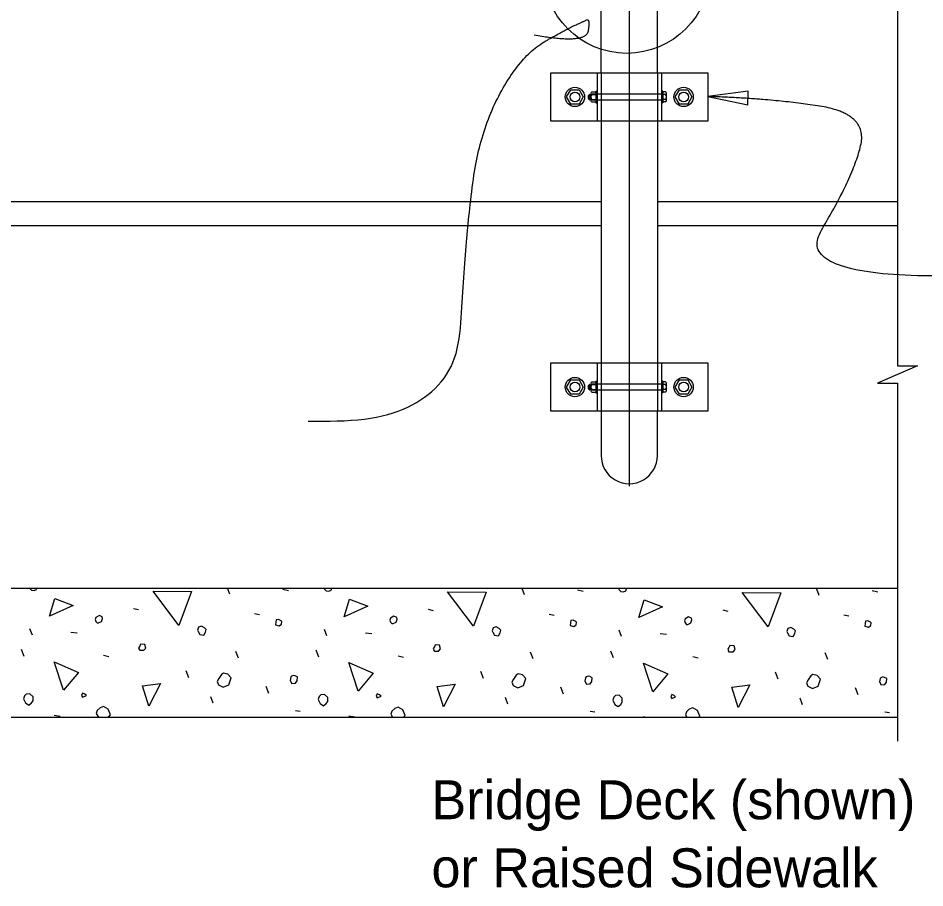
# Model space of a CAD drawing. Extents: x 0.5 to 39.7, y 0.9 to 25.6.
# Drawn here: x 19.046 to 23.735, y 12.586 to 17.084 of the extents above; entities that cross this region are included whole.
import ezdxf

# ---------------------------------------------------------------- set-up
doc = ezdxf.new("R2010")
doc.units = 0
for name, color, linetype in [('CL_Major', 7, 'Continuous'), ('Dimension', 7, 'Continuous'), ('Miscellaneous', 7, 'Continuous'), ('SteelMisc', 7, 'Continuous'), ('SteelMisc_h', 7, 'Continuous'), ('SupstrConc', 7, 'Continuous')]:
    doc.layers.add(name, color=color, linetype=linetype)

msp = doc.modelspace()

# ---------------------------------------------------------------- linework, layer by layer
at = {"layer": 'CL_Major'}
msp.add_line((22.2062, 25.5043), (22.2062, 14.6639), dxfattribs=at)
at = {"layer": 'Dimension'}
for points in [[(23.5932, 20.1983), (23.5932, 19.1806), (23.6966, 19.1806), (23.5932, 19.1356), (23.4899, 19.0906), (23.5932, 19.0906), (23.5932, 16.8862)], [(23.5932, 17.1362), (23.5932, 15.2854), (23.6966, 15.2854), (23.5932, 15.2404), (23.4899, 15.1954), (23.5932, 15.1954), (23.5932, 13.3448)]]:
    msp.add_lwpolyline(points, dxfattribs=at)
msp.add_lwpolyline([(22.6122, 16.6783), (22.819, 16.6352), (22.8216, 16.7057)], close=True, dxfattribs=at)
msp.add_circle((22.1934, 17.3332), 0.4318, dxfattribs=at)
for points in [[(20.5456, 14.9991), (21.3049, 14.9652), (21.3652, 16.0213), (21.4405, 16.5191), (21.6515, 16.8963), (21.8903, 17.0313), (21.9647, 17.0631), (22.0043, 17.0848), (21.982, 16.9466), (21.7151, 16.9952)], [(23.9932, 15.7529), (23.0399, 15.7236), (23.3618, 16.2556), (23.4433, 16.5898), (22.9335, 16.6682), (22.6122, 16.6783)]]:
    msp.add_open_spline(points, degree=2, dxfattribs=at)
at = {"layer": 'Miscellaneous'}
for p, q in [((21.9986, 16.6691), (21.9986, 16.6812)), ((22.0044, 16.6691), (22.0044, 16.6812)), ((21.9986, 15.1691), (21.9986, 15.1812)), ((22.0044, 15.1691), (22.0044, 15.1812)), ((20.141, 14.1043), (20.1292, 14.1361)), ((20.415, 14.1308), (20.4432, 14.1237)), ((21.6648, 14.1008), (21.6524, 14.1344)), ((21.9388, 14.1273), (21.9671, 14.1202)), ((23.1886, 14.0972), (23.1762, 14.1308)), ((23.4626, 14.1237), (23.4909, 14.1167)), ((19.6424, 14.0301), (19.669, 14.0247)), ((21.1663, 14.0265), (21.1928, 14.0212)), ((22.6901, 14.023), (22.7166, 14.0177)), ((20.2682, 14.0053), (20.2947, 14)), ((21.792, 14.0018), (21.8186, 13.9965)), ((23.3159, 13.9982), (23.3424, 13.9929)), ((19.1192, 13.8922), (19.1068, 13.9258)), ((19.3189, 13.9081), (19.3508, 13.9045)), ((20.643, 13.8886), (20.6306, 13.9222)), ((20.8428, 13.9045), (20.8746, 13.901)), ((22.1668, 13.8851), (22.1544, 13.9187)), ((22.3666, 13.901), (22.3984, 13.8975)), ((19.0768, 13.7826), (19.0626, 13.8179)), ((19.4869, 13.7896), (19.5152, 13.7826)), ((20.1851, 13.7737), (20.171, 13.8091)), ((20.6006, 13.779), (20.5864, 13.8144)), ((21.0107, 13.7861), (21.039, 13.779)), ((21.709, 13.7702), (21.6948, 13.8055)), ((22.1244, 13.7755), (22.1102, 13.8108)), ((23.2328, 13.7667), (23.2186, 13.802)), ((22.5345, 13.7826), (22.5628, 13.7755)), ((19.9288, 13.673), (19.9147, 13.7083)), ((21.4526, 13.6694), (21.4385, 13.7048)), ((22.9765, 13.6659), (22.9623, 13.7012)), ((20.3425, 13.5916), (20.3283, 13.627)), ((21.8663, 13.5881), (21.8522, 13.6235)), ((23.3901, 13.5846), (23.376, 13.6199)), ((20.0543, 13.5404), (20.042, 13.574)), ((21.5781, 13.5368), (21.5658, 13.5704)), ((23.102, 13.5333), (23.0896, 13.5669)), ((19.2323, 13.4785), (19.2624, 13.4732)), ((20.4804, 13.5033), (20.5051, 13.4997)), ((20.7561, 13.475), (20.7862, 13.4697)), ((22.0042, 13.4997), (22.0289, 13.4962)), ((22.28, 13.4714), (22.2912, 13.4695)), ((23.528, 13.4962), (23.5527, 13.4927))]:
    msp.add_line(p, q, dxfattribs=at)
for points in [[(19.105, 14.1361), (19.1156, 14.1255)], [(19.1156, 14.1255), (19.128, 14.1237), (19.1404, 14.129), (19.1428, 14.1361)], [(19.8776, 13.9434), (19.7432, 14.1202), (19.943, 14.1184), (19.8776, 13.9434)], [(20.63, 14.1361), (20.6289, 14.1326), (20.6395, 14.122)], [(20.6395, 14.122), (20.6518, 14.1202), (20.6642, 14.1255), (20.6677, 14.1361)], [(21.4014, 13.9399), (21.267, 14.1167), (21.4668, 14.1149), (21.4014, 13.9399)], [(22.155, 14.1361), (22.1527, 14.129), (22.1633, 14.1184)], [(22.1633, 14.1184), (22.1757, 14.1167), (22.188, 14.122), (22.1916, 14.1326), (22.1894, 14.1361)], [(19.2076, 13.9912), (19.2359, 14.0831), (19.3295, 14.046), (19.2076, 13.9912)], [(20.7314, 13.9876), (20.7597, 14.0796), (20.8534, 14.0424), (20.7314, 13.9876)], [(22.2552, 13.9841), (22.2835, 14.076), (22.3772, 14.0389), (22.2552, 13.9841)], [(22.9252, 13.9364), (22.7908, 14.1131), (22.9906, 14.1114), (22.9252, 13.9364)], [(19.4551, 13.9558), (19.4621, 13.9558), (19.4763, 13.9629), (19.4816, 13.9788), (19.4798, 13.9876), (19.4657, 13.9947), (19.448, 13.9841), (19.4445, 13.9735), (19.448, 13.9629), (19.4551, 13.9558)], [(20.3761, 13.947), (20.3955, 13.9417), (20.4079, 13.9505), (20.4097, 13.9629), (20.4061, 13.9664), (20.392, 13.9735), (20.3796, 13.9717), (20.3778, 13.9593), (20.3761, 13.947)], [(20.9789, 13.9523), (20.9859, 13.9523), (21.0001, 13.9593), (21.0054, 13.9753), (21.0036, 13.9841), (20.9895, 13.9912), (20.9718, 13.9806), (20.9683, 13.9699), (20.9718, 13.9593), (20.9789, 13.9523)], [(22.5027, 13.9487), (22.5098, 13.9487), (22.5239, 13.9558), (22.5292, 13.9717), (22.5274, 13.9806), (22.5133, 13.9876), (22.4956, 13.977), (22.4921, 13.9664), (22.4956, 13.9558), (22.5027, 13.9487)], [(19.9766, 13.9116), (19.9854, 13.8957), (20.0066, 13.8922), (20.0154, 13.9081), (20.019, 13.9222), (20.0101, 13.9311), (19.9942, 13.9399), (19.9783, 13.9346), (19.973, 13.9187), (19.9766, 13.9116)], [(21.5004, 13.9081), (21.5092, 13.8922), (21.5304, 13.8886), (21.5393, 13.9045), (21.5428, 13.9187), (21.534, 13.9275), (21.518, 13.9364), (21.5021, 13.9311), (21.4968, 13.9151), (21.5004, 13.9081)], [(21.8999, 13.9434), (21.9193, 13.9381), (21.9317, 13.947), (21.9335, 13.9593), (21.9299, 13.9629), (21.9158, 13.9699), (21.9034, 13.9682), (21.9016, 13.9558), (21.8999, 13.9434)], [(23.0242, 13.9045), (23.033, 13.8886), (23.0542, 13.8851), (23.0631, 13.901), (23.0666, 13.9151), (23.0578, 13.924), (23.0419, 13.9328), (23.0259, 13.9275), (23.0206, 13.9116), (23.0242, 13.9045)], [(23.4237, 13.9399), (23.4431, 13.9346), (23.4555, 13.9434), (23.4573, 13.9558), (23.4537, 13.9593), (23.4396, 13.9664), (23.4272, 13.9646), (23.4255, 13.9523), (23.4237, 13.9399)], [(19.6743, 13.8144), (19.6955, 13.8144), (19.7061, 13.825), (19.7008, 13.8444), (19.6778, 13.8462), (19.6743, 13.8356), (19.669, 13.8268), (19.6743, 13.8144), (19.6707, 13.8179)], [(21.1981, 13.8108), (21.2193, 13.8108), (21.2299, 13.8215), (21.2246, 13.8409), (21.2016, 13.8427), (21.1981, 13.8321), (21.1928, 13.8232), (21.1981, 13.8108), (21.1945, 13.8144)], [(22.7219, 13.8073), (22.7431, 13.8073), (22.7537, 13.8179), (22.7484, 13.8374), (22.7254, 13.8391), (22.7219, 13.8285), (22.7166, 13.8197), (22.7219, 13.8073), (22.7184, 13.8108)], [(19.2801, 13.6076), (19.2323, 13.7543), (19.3578, 13.6995), (19.2801, 13.6076)], [(20.8039, 13.604), (20.7561, 13.7507), (20.8816, 13.6959), (20.8039, 13.604)], [(22.3277, 13.6005), (22.28, 13.7472), (22.4055, 13.6924), (22.3277, 13.6005)], [(20.0826, 13.6358), (20.1056, 13.6235), (20.1356, 13.6358), (20.148, 13.673), (20.1303, 13.6906), (20.1074, 13.6959), (20.0968, 13.6889), (20.0844, 13.6694), (20.0755, 13.6535), (20.0826, 13.6358)], [(21.6064, 13.6323), (21.6294, 13.6199), (21.6595, 13.6323), (21.6718, 13.6694), (21.6542, 13.6871), (21.6312, 13.6924), (21.6206, 13.6853), (21.6082, 13.6659), (21.5994, 13.65), (21.6064, 13.6323)], [(20.4521, 13.6588), (20.4609, 13.6429), (20.4804, 13.6447), (20.4892, 13.6571), (20.491, 13.6765), (20.4786, 13.6818), (20.4698, 13.6836), (20.4592, 13.68), (20.4556, 13.6765), (20.4521, 13.6588)], [(21.9759, 13.6553), (21.9847, 13.6394), (22.0042, 13.6411), (22.013, 13.6535), (22.0148, 13.673), (22.0024, 13.6783), (21.9936, 13.68), (21.983, 13.6765), (21.9794, 13.673), (21.9759, 13.6553)], [(23.1302, 13.6288), (23.1532, 13.6164), (23.1833, 13.6288), (23.1957, 13.6659), (23.178, 13.6836), (23.155, 13.6889), (23.1444, 13.6818), (23.132, 13.6624), (23.1232, 13.6464), (23.1302, 13.6288)], [(23.4997, 13.6518), (23.5085, 13.6358), (23.528, 13.6376), (23.5368, 13.65), (23.5386, 13.6694), (23.5262, 13.6747), (23.5174, 13.6765), (23.5068, 13.673), (23.5032, 13.6694), (23.4997, 13.6518)], [(19.722, 13.5262), (19.6884, 13.6305), (19.7821, 13.6429), (19.722, 13.5262)], [(21.2458, 13.5227), (21.2122, 13.627), (21.3059, 13.6394), (21.2458, 13.5227)], [(22.7696, 13.5192), (22.736, 13.6235), (22.8297, 13.6358), (22.7696, 13.5192)], [(19.0732, 13.5634), (19.0838, 13.5421), (19.1015, 13.5315), (19.1156, 13.5421), (19.1227, 13.5528), (19.1227, 13.574), (19.1068, 13.5899), (19.0874, 13.5881), (19.0785, 13.5793), (19.0732, 13.5634)], [(19.379, 13.5722), (19.3985, 13.581), (19.3914, 13.5881), (19.379, 13.5934), (19.3737, 13.581), (19.379, 13.5722)], [(20.597, 13.5598), (20.6076, 13.5386), (20.6253, 13.528), (20.6395, 13.5386), (20.6465, 13.5492), (20.6465, 13.5704), (20.6306, 13.5863), (20.6112, 13.5846), (20.6023, 13.5757), (20.597, 13.5598)], [(20.9029, 13.5687), (20.9223, 13.5775), (20.9152, 13.5846), (20.9029, 13.5899), (20.8976, 13.5775), (20.9029, 13.5687)], [(22.1209, 13.5563), (22.1315, 13.5351), (22.1491, 13.5245), (22.1633, 13.5351), (22.1703, 13.5457), (22.1703, 13.5669), (22.1544, 13.5828), (22.135, 13.581), (22.1262, 13.5722), (22.1209, 13.5563)], [(22.4267, 13.5651), (22.4461, 13.574), (22.4391, 13.581), (22.4267, 13.5863), (22.4214, 13.574), (22.4267, 13.5651)], [(19.5132, 13.4695), (19.524, 13.4803), (19.5116, 13.5103), (19.4869, 13.5245), (19.4692, 13.5174), (19.4551, 13.5033), (19.4498, 13.4873)], [(21.0405, 13.4695), (21.0478, 13.4767), (21.0354, 13.5068), (21.0107, 13.5209), (20.993, 13.5139), (20.9789, 13.4997), (20.9736, 13.4838)], [(22.5679, 13.4695), (22.5716, 13.4732), (22.5593, 13.5033), (22.5345, 13.5174), (22.5168, 13.5103), (22.5027, 13.4962), (22.4974, 13.4803)], [(19.4498, 13.4873), (19.4608, 13.4695)], [(20.9736, 13.4838), (20.9825, 13.4695)], [(22.4974, 13.4803), (22.5041, 13.4695)]]:
    msp.add_lwpolyline(points, dxfattribs=at)
at = {"layer": 'SteelMisc'}
for p, q in [((22.0604, 16.801), (22.0604, 17.4631)), ((22.3521, 16.801), (22.3521, 17.4631)), ((21.8002, 16.801), (22.6122, 16.801)), ((21.8002, 16.551), (21.8002, 16.801)), ((22.0396, 16.801), (22.0396, 16.551)), ((22.3729, 16.801), (22.3729, 16.551)), ((22.6122, 16.801), (22.6122, 16.551)), ((22.008, 16.6939), (22.008, 16.6582)), ((22.0129, 16.702), (22.033, 16.702)), ((22.033, 16.7063), (22.033, 16.6457)), ((22.033, 16.7063), (22.0396, 16.7063)), ((22.033, 16.702), (22.033, 16.65)), ((22.3792, 16.7063), (22.3731, 16.7063)), ((22.3939, 16.702), (22.3791, 16.702)), ((22.3792, 16.7063), (22.3792, 16.6457)), ((22.399, 16.6566), (22.399, 16.6955)), ((21.9958, 16.684), (22.0015, 16.6906)), ((21.9958, 16.6663), (21.9958, 16.684)), ((21.9958, 16.6663), (22.0015, 16.6607)), ((22.0015, 16.6906), (22.008, 16.6906)), ((22.0015, 16.6607), (22.0015, 16.6906)), ((22.0015, 16.6607), (22.008, 16.6607)), ((22.0127, 16.689), (22.033, 16.689)), ((22.0127, 16.6631), (22.033, 16.6631)), ((22.013, 16.65), (22.033, 16.65)), ((22.394, 16.689), (22.3791, 16.689)), ((22.394, 16.663), (22.3791, 16.663)), ((22.3939, 16.65), (22.3791, 16.65)), ((22.033, 16.6457), (22.0396, 16.6457)), ((22.3792, 16.6457), (22.3731, 16.6457)), ((22.6122, 16.551), (21.8002, 16.551)), ((22.0604, 16.551), (22.0604, 15.301)), ((22.3521, 16.551), (22.3521, 15.301)), ((21.8002, 15.301), (22.6122, 15.301)), ((21.8002, 15.051), (21.8002, 15.301)), ((22.0396, 15.301), (22.0396, 15.051)), ((22.3729, 15.301), (22.3729, 15.051)), ((22.6122, 15.301), (22.6122, 15.051)), ((22.008, 15.1939), (22.008, 15.1582)), ((22.0129, 15.202), (22.033, 15.202)), ((22.033, 15.2063), (22.033, 15.1457)), ((22.033, 15.2063), (22.0396, 15.2063)), ((22.033, 15.202), (22.033, 15.15)), ((22.3792, 15.2063), (22.3731, 15.2063)), ((22.3939, 15.202), (22.3791, 15.202)), ((22.3792, 15.2063), (22.3792, 15.1457)), ((22.399, 15.1566), (22.399, 15.1955)), ((21.9958, 15.184), (22.0015, 15.1906)), ((21.9958, 15.1663), (21.9958, 15.184)), ((21.9958, 15.1663), (22.0015, 15.1607)), ((22.0015, 15.1906), (22.008, 15.1906)), ((22.0015, 15.1607), (22.0015, 15.1906)), ((22.0015, 15.1607), (22.008, 15.1607)), ((22.0127, 15.189), (22.033, 15.189)), ((22.0127, 15.1631), (22.033, 15.1631)), ((22.013, 15.15), (22.033, 15.15)), ((22.394, 15.189), (22.3791, 15.189)), ((22.394, 15.163), (22.3791, 15.163)), ((22.3939, 15.15), (22.3791, 15.15)), ((22.033, 15.1457), (22.0396, 15.1457)), ((22.3792, 15.1457), (22.3731, 15.1457)), ((22.6122, 15.051), (21.8002, 15.051)), ((22.0603, 15.051), (22.0603, 14.8218)), ((22.3519, 14.8218), (22.3519, 15.051))]:
    msp.add_line(p, q, dxfattribs=at)
for points in [[(21.9036, 16.7135), (21.9469, 16.7135), (21.9686, 16.676), (21.9469, 16.6385), (21.9036, 16.6385), (21.8819, 16.676)], [(22.4655, 16.7135), (22.5089, 16.7135), (22.5305, 16.676), (22.5089, 16.6385), (22.4655, 16.6385), (22.4439, 16.676)], [(21.9036, 15.2135), (21.9469, 15.2135), (21.9686, 15.176), (21.9469, 15.1385), (21.9036, 15.1385), (21.8819, 15.176)], [(22.4655, 15.2135), (22.5089, 15.2135), (22.5305, 15.176), (22.5089, 15.1385), (22.4655, 15.1385), (22.4439, 15.176)]]:
    msp.add_lwpolyline(points, close=True, dxfattribs=at)
for centre, radius in [((21.9252, 16.676), 0.05), ((21.9252, 16.676), 0.025), ((22.4872, 16.676), 0.05), ((22.4872, 16.676), 0.025), ((21.9252, 15.176), 0.05), ((21.9252, 15.176), 0.025), ((22.4872, 15.176), 0.05), ((22.4872, 15.176), 0.025)]:
    msp.add_circle(centre, radius, dxfattribs=at)
for centre, radius, start, end in [((22.0145, 16.6955), 0.00674, 104.4891, 254.1889), ((22.3922, 16.6955), 0.00673, 285.7823, 75.5404), ((22.0274, 16.676), 0.0196, 138.628, 221.372), ((22.0145, 16.6565), 0.00673, 105.7823, 255.5404), ((22.3922, 16.6565), 0.00674, 284.4891, 74.1889), ((22.3793, 16.676), 0.0196, 318.628, 41.372), ((22.0145, 15.1955), 0.00674, 104.4891, 254.1889), ((22.3922, 15.1955), 0.00673, 285.7823, 75.5404), ((22.0274, 15.176), 0.0196, 138.628, 221.372), ((22.0145, 15.1565), 0.00673, 105.7823, 255.5404), ((22.3922, 15.1565), 0.00674, 284.4891, 74.1889), ((22.3793, 15.176), 0.0196, 318.628, 41.372)]:
    msp.add_arc(centre, radius, start, end, dxfattribs=at)
msp.add_ellipse((22.2062, 14.8218), major_axis=(0, 0.1458), ratio=0.999499, start_param=1.570796, end_param=4.712389, dxfattribs=at)
at = {"layer": 'SteelMisc_h'}
for p, q in [((22.0604, 16.801), (22.0604, 16.551)), ((22.3521, 16.801), (22.3521, 16.551)), ((22.3729, 16.6906), (22.008, 16.6906)), ((22.008, 16.6607), (22.3729, 16.6607)), ((22.0604, 15.301), (22.0604, 15.051)), ((22.3521, 15.301), (22.3521, 15.051)), ((22.3729, 15.1906), (22.008, 15.1906)), ((22.008, 15.1607), (22.3729, 15.1607))]:
    msp.add_line(p, q, dxfattribs=at)
at = {"layer": 'SupstrConc'}
for p, q in [((12.3521, 16.1361), (22.0604, 16.1361)), ((22.3521, 16.1361), (23.5931, 16.1361)), ((12.3521, 16.0111), (22.0604, 16.0111)), ((22.3521, 16.0111), (23.5931, 16.0111)), ((0.8193, 14.1361), (23.5931, 14.1361)), ((0.8193, 13.4695), (23.5931, 13.4695))]:
    msp.add_line(p, q, dxfattribs=at)

# ---------------------------------------------------------------- texts
at = {"layer": 'Dimension'}
for s, p in [('Bridge Deck (shown)', (21.1833, 12.9409)), ('or Raised Sidewalk', (21.1833, 12.5889))]:
    msp.add_text(s, height=0.2016, dxfattribs=at).set_placement(p)

doc.saveas('drawing.dxf')
